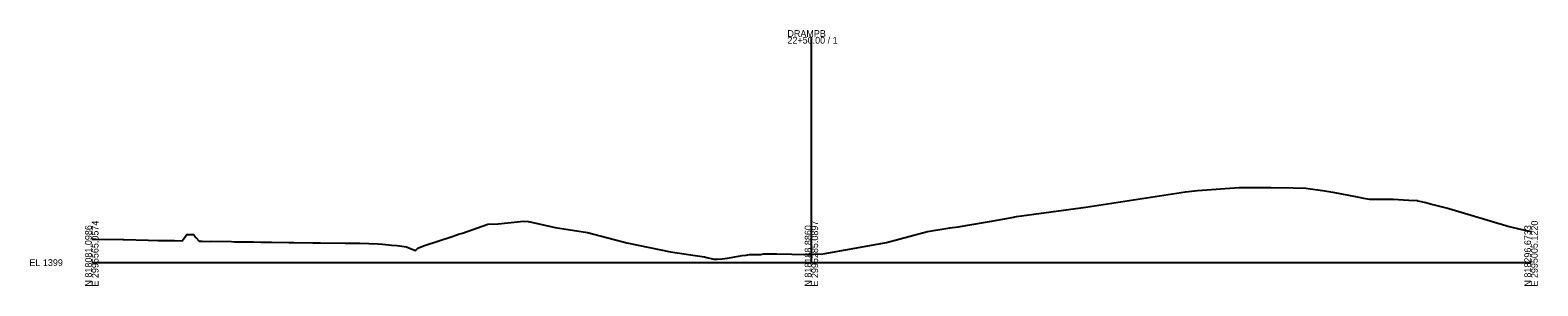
# Model space of a CAD drawing. Extents: x -26 to 2995414, y -63 to 818393.
# Drawn here: x -26 to 603, y 2990 to 3097 of the extents above; entities that cross this region are included whole.
import ezdxf

# ---------------------------------------------------------------- set-up
doc = ezdxf.new("R2010")
doc.units = 0
doc.layers.add('DESIGN - SHEET - Light Grid', color=7, linetype='Continuous')
doc.layers.add('SURVEY - GROUND - Top of Ground', color=7, linetype='Continuous')

msp = doc.modelspace()

# ---------------------------------------------------------------- linework, layer by layer
at = {"layer": 'DESIGN - SHEET - Light Grid'}
for p, q in [((300, 3000), (300, 3094.09)), ((0, 3000), (300, 3000)), ((300, 3000), (600, 3000))]:
    msp.add_line(p, q, dxfattribs=at)
at = {"layer": 'SURVEY - GROUND - Top of Ground'}
msp.add_lwpolyline([(0, 3009.77), (1.62, 3009.75), (12.88, 3009.58), (13.36, 3009.57), (23.45, 3009.35), (27.73, 3009.27), (31.96, 3009.18), (34.47, 3009.14), (37.64, 3009.09), (38.45, 3010.13), (39.67, 3011.72), (41.84, 3011.68), (42.34, 3011.68), (42.48, 3011.52), (43.39, 3010.48), (44.76, 3008.91), (45.98, 3008.87), (49.09, 3008.86), (50.08, 3008.87), (58.26, 3008.74), (59.49, 3008.72), (67.62, 3008.59), (70.45, 3008.54), (74.88, 3008.48), (82.14, 3008.35), (82.72, 3008.34), (84.19, 3008.32), (92.13, 3008.25), (95.37, 3008.21), (105.61, 3008.14), (106.57, 3008.13), (108.19, 3008.11), (111.76, 3008.04), (119.3, 3007.81), (121.22, 3007.64), (124.96, 3007.31), (127.37, 3007.12), (131.16, 3006.5), (132.42, 3006.02), (135, 3005.05), (135.94, 3006.02), (138.29, 3006.93), (150.65, 3011.01), (152.91, 3011.91), (154.55, 3012.29), (165.07, 3016), (169.36, 3016.19), (180.1, 3017.29), (181.86, 3017.07), (183.36, 3016.83), (193.22, 3014.65), (206.72, 3012.57), (223.01, 3008.3), (241.19, 3004.46), (251.52, 3003), (255.37, 3002.39), (255.78, 3002.25), (259.37, 3001.37), (260.77, 3001.45), (262.76, 3001.58), (265.03, 3001.9), (271.12, 3002.99), (272.77, 3003.12), (274.24, 3003.31), (278.85, 3003.44), (280.05, 3003.71), (282.3, 3003.72), (283.33, 3003.68), (284.48, 3003.63), (285.62, 3003.62), (291.84, 3003.57), (298.57, 3003.4), (300.09, 3003.37), (301.04, 3003.49), (304.93, 3003.68), (331.25, 3008.31), (348.38, 3012.93), (357.73, 3014.45), (361.24, 3014.84), (378.34, 3017.85), (383.52, 3018.84), (385.44, 3019.23), (414.45, 3023.09), (455.91, 3029.54), (460.89, 3030.12), (478.28, 3031.36), (491.46, 3031.34), (500.87, 3031.21), (506.09, 3031.01), (513.97, 3029.95), (517.34, 3029.3), (527.48, 3027.35), (530.18, 3026.83), (531.89, 3026.51), (532.68, 3026.5), (533.49, 3026.49), (533.88, 3026.45), (536.22, 3026.44), (538.63, 3026.44), (542.59, 3026.42), (549.07, 3026.02), (552.66, 3025.92), (552.71, 3025.77), (554.23, 3025.44), (554.7, 3025.34), (556.13, 3025), (559.13, 3024.27), (565.77, 3022.48), (590.86, 3014.99), (594.85, 3014.02), (600, 3012.91)], dxfattribs=at)

# ---------------------------------------------------------------- texts
at = {"layer": 'DESIGN - SHEET - Light Grid'}
for s, p in [('22+50.00 / 1', (290, 3091.29)), ('DRAMPB', (290, 3094.09)), ('EL 1399', (-26, 2998.6))]:
    msp.add_text(s, height=2.8, dxfattribs=at).set_placement(p)
for s, p in [('E 2995565.0574', (2.8, 2990)), ('E 2995285.0897', (302.8, 2990)), ('E 2995005.1220', (602.8, 2990)), ('N 818081.0986', (0, 2990)), ('N 818188.8860', (300, 2990)), ('N 818296.6733', (600, 2990))]:
    msp.add_text(s, height=2.8, rotation=90, dxfattribs=at).set_placement(p)

doc.saveas('drawing.dxf')
